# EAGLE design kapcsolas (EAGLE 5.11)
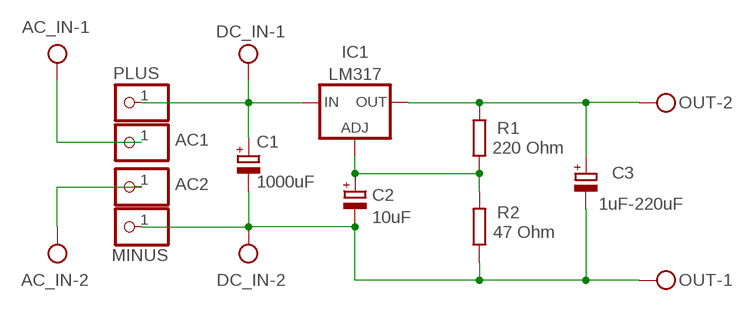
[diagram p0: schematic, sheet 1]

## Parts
AC1  PINHD-1X1  [1X01]
AC2  PINHD-1X1  [1X01]
AC_IN  MKDSN1,5/2-5,08  [MKDSN1,5/2-5,08]
C1  1000uF  CPOL-EUE3.5-8  [E3,5-8]
C2  10uF  CPOL-EUE2.5-6  [E2,5-6]
C3  1uF-220uF  CPOL-EUE3.5-8  [E3,5-8]
DC_IN  MKDSN1,5/2-5,08  [MKDSN1,5/2-5,08]
IC1  LM317  LM317TL  [317TL]
MINUS  PINHD-1X1  [1X01]
OUT  MKDSN1,5/2-5,08  [MKDSN1,5/2-5,08]
PLUS  PINHD-1X1  [1X01]
R1  220 Ohm  R-EU_0207/10  [0207/10]
R2  47 Ohm  R-EU_0207/10  [0207/10]

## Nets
N$1: AC2.1 AC_IN.2
N$2: AC1.1 AC_IN.1
N$5: C1.+ DC_IN.1 IC1.3(IN) PLUS.1
N$8: C2.+ IC1.1(ADJ) R1.1 R2.2
N$9: C3.+ IC1.2(OUT) OUT.2 R1.2
N$11: C1.- C2.- C3.- DC_IN.2 MINUS.1 OUT.1 R2.1

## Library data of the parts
AC1 AC2 MINUS PLUS = pinhead:PINHD-1X1: PIN HEADER
AC_IN DC_IN OUT = con-phoenix-508:MKDSN1,5/2-5,08: MKDSN 1,5/ 2-5,08 Printklemme; MPN: MKDSN 1,5/2-5.08; OC_FARNELL: 1792903; OC_NEWARK: 30M2397
C1-C3 = resistor:CPOL-EU: POLARIZED CAPACITOR, European symbol
IC1 = v-reg:LM317TL: VOLTAGE REGULATOR
R1 R2 = resistor:R-EU_: RESISTOR, European symbol

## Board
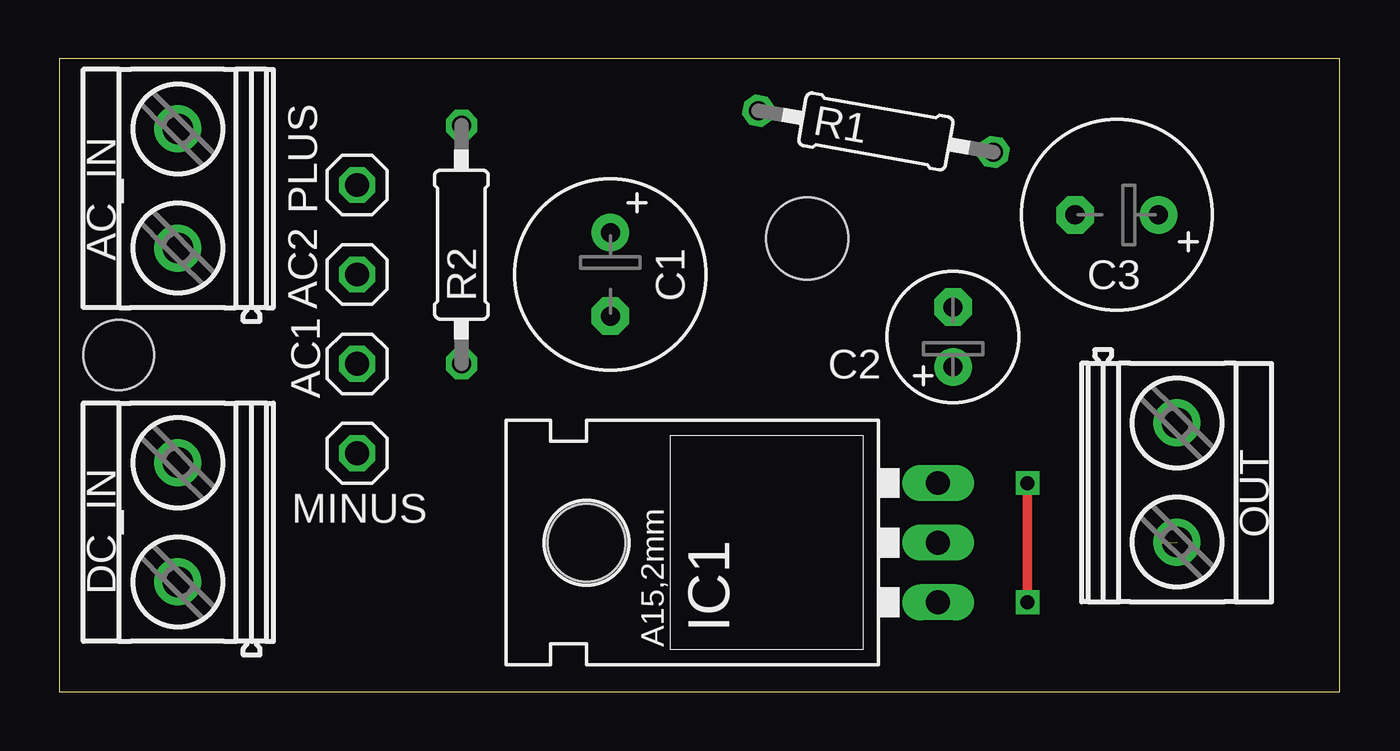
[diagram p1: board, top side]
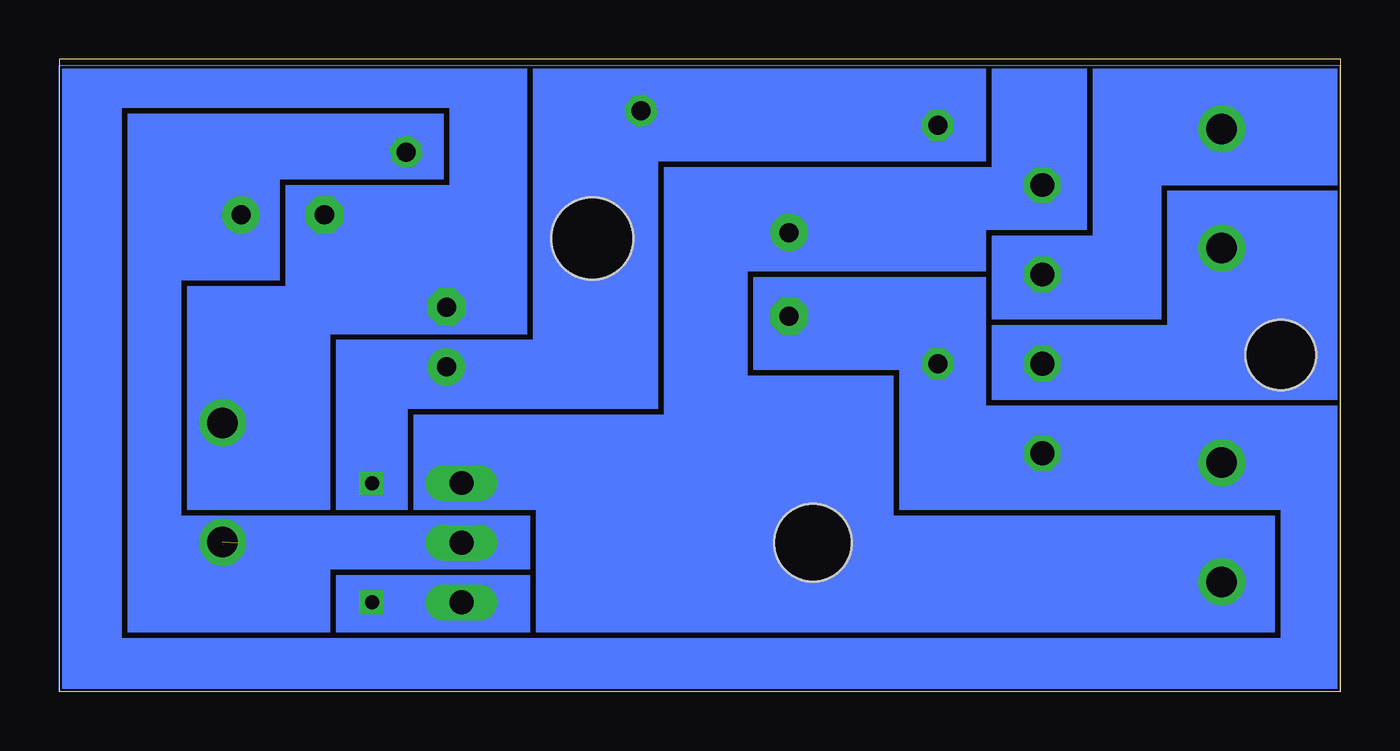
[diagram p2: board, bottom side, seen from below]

Size 54.59 x 26.98 mm. Coordinates in mm from the lower left corner, seen from the top.
Outline: 0,0 54.59,0 54.59,26.98 0,26.98 0,0
Copper layers (1*16): Top 0.035mm / dielectric 1.5mm / Bottom 0.035mm
Design rules "default": minimum track width 10mil, minimum drill 24mil, track to track 8mil, track to pad 8mil, pad to pad 8mil, via to via 8mil, smd to smd 8mil, copper to edge 40mil, drill to drill 8mil, minimum pad ring 10mil, minimum via ring 8mil, stop-mask expansion 4mil, vias tented up to drill 0mil, thermal gap 10mil
Holes 3.5 mm at 31.88,19.3
Holes 3 mm at 2.54,14.35

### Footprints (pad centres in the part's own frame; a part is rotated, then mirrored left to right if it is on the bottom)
1X01 = drill 1.016 octagon: 1 0,0
MKDSN1,5/2-5,08 = drill 1.3 pad 2 round: 1 -2.561,0.025; 2 2.519,0.025
E3,5-8 = drill 0.813 pad 1.6 round: + -1.778,0 | drill 0.813 pad 1.6 octagon: - 1.778,0
E2,5-6 = drill 0.813 pad 1.6 round: + -1.27,0 | drill 0.813 pad 1.6 octagon: - 1.27,0
317TL = drill 1.016 long: 1 -2.54,-3.81; 2 0,-3.81; 3 2.54,-3.81 | hole 3.302: 0,11.176
0207/10 = drill 0.813 octagon: 1 -5.08,0; 2 5.08,0

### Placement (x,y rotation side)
AC1  12.7,13.97 0 top
AC2  12.7,17.78 0 top
AC_IN  5.08,21.46 90 top
C1  23.5,17.78 270 top
C2  38.1,15.11 90 top
C3  45.09,20.32 180 top
DC_IN  5.08,7.24 90 top
IC1  33.66,6.35 90 top
MINUS  12.7,10.16 0 top
OUT  47.62,8.89 270 top
PLUS  12.7,21.59 0 top
R1  34.82,23.88 350 top
R2  17.14,19.05 90 top

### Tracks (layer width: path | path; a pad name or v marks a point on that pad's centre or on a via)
N$1
  Bottom 0.406: AC2.1 9.53,17.78 9.53,23.5 5.08,23.5 5.08,24.13 5.05,24.13 AC_IN.2
N$2
  Bottom 0.406: AC1.1 5.05,13.97 AC_IN.1
N$3
  Bottom 0.025: 0,0 54.61,0 54.61,26.67 0,26.67 0,0
N$5
  Bottom 0.406: PLUS.1 23.5,21.59 23.5,20.32 | 23.5,20.32 C1.+ | DC_IN.1 19.68,5.05 19.68,12.7 26.04,12.7 | 26.04,12.7 26.04,20.32 23.5,20.32 | 26.04,12.7 26.04,11.43 37.47,11.43 IC1.3
N$8  (via drill 0.6)
  Top 0.406: v41.27,8.89 v41.27,3.81
  Bottom 0.406: C2.+ 31.11,14.61 R1.1 28.57,24.13 R2.2 | C2.+ 32.38,13.97 | C2.+ 41.27,13.97 v41.27,8.89 | v41.27,3.81 IC1.1
N$9  (1 unrouted)
  Bottom 0.406: IC1.2 46.99,6.33 50.8,6.33 50.8,20.32 C3.+ 47.62,20.32 47.62,22.86 R1.2
N$11
  Bottom 0.406: MINUS.1 17.14,10.16 R2.1 17.14,16.51 23.5,16.51 C1.- | MINUS.1 3.2,10.16 DC_IN.2 | C2.- 34.92,16.51 | C2.- 43.31,16.51 | 43.31,16.51 C3.- | 43.31,16.51 46.35,12.04 47.65,11.41 OUT.1 | MINUS.1 1.91,10.16 1.91,1.27 52.7,1.27 52.7,25.4 34.92,25.4 C2.-
(copper drawn outside any net)
  shapes: Bottom area x65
